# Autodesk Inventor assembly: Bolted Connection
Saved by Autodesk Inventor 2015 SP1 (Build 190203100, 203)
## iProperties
Created: 2011-06
Part Number: Bolted Connection
Document SubType Name: Assembly
Designer: Guilherme Augusto Franco de Souza
ClientObjectVersion: 1
Author: Guilherme Augusto Franco de Souza
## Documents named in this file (4)
- E:\Visitor Experience Project\WSI2015 - Visitor Experience Project\#46- Sheet Metal Technology\01- 3D Models\Outodoor Heater\2- Assemblies\Outdoor Burner\Design Accelerator\Bolted Connection4.iam
- C:\Users\Guilherme Augusto\Documents\Inventor\Content Center Files\R2015\en-US\ISO 7089\ISO 7089 - 3 - 140 HV(1).ipt
- C:\Users\Guilherme Augusto\Documents\Inventor\Content Center Files\R2015\en-US\ISO 4017(1)\ISO 4017 - M3 x 10ISO.ipt
- C:\Users\Guilherme Augusto\Documents\Inventor\Content Center Files\R2015\en-US\ISO 4032(2)\ISO 4032 - M3ISO.ipt
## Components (8 placed, 3 different names)
1. ISO 7089 3 - 140 HV:5
2. ISO 4017 M3 x 10:3
3. ISO 7089 3 - 140 HV:6
4. ISO 4032 M3:3
5. ISO 4017 M3 x 10:4
6. ISO 7089 3 - 140 HV:7
7. ISO 7089 3 - 140 HV:8
8. ISO 4032 M3:4
